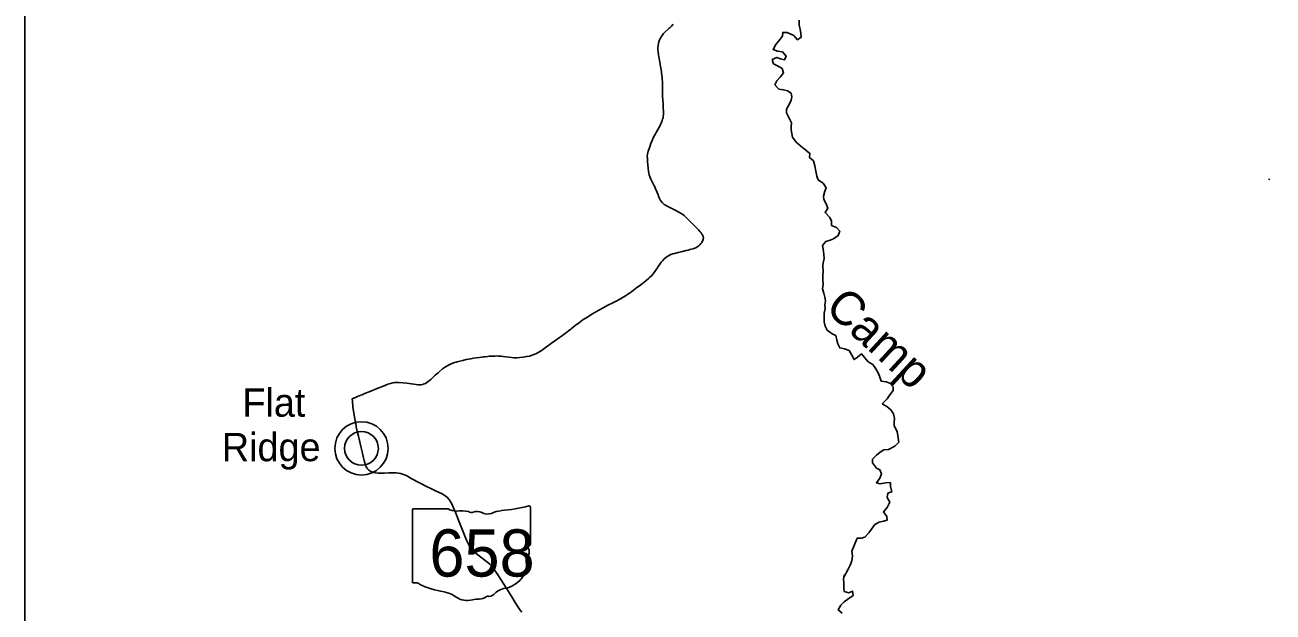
# Model space of a CAD drawing. Extents: x -29.6 to 34, y 0 to 22.
# Drawn here: x -29.583 to -26.314, y 9.402 to 10.939 of the extents above; entities that cross this region are included whole.
import ezdxf

# ---------------------------------------------------------------- set-up
doc = ezdxf.new("R2010")
doc.units = 0
for name, color, linetype in [('GM_X_Minor_River', 7, 'Continuous'), ('GM_X_Minor_River_Text', 7, 'Continuous'), ('GM_X_State_Route', 7, 'Continuous'), ('GM_X_State_Shield', 7, 'Continuous'), ('GM_X_Township_Road', 7, 'Continuous'), ('GM_X_Unincorporated', 7, 'Continuous'), ('GM_X_Unincorporated_Location', 7, 'Continuous'), ('GM_X_Unincorporated_Text', 7, 'Continuous'), ('SH_Text', 7, 'Continuous')]:
    doc.layers.add(name, color=color, linetype=linetype)

msp = doc.modelspace()

# ---------------------------------------------------------------- linework, layer by layer
at = {"layer": 'GM_X_Minor_River'}
msp.add_line((-26.3226, 10.534), (-26.3259, 10.5356), dxfattribs=at)
for points in [[(-27.5556, 10.9516), (-27.5555, 10.9388), (-27.5533, 10.9279), (-27.5507, 10.9162), (-27.5506, 10.9066), (-27.5601, 10.9001), (-27.5698, 10.911), (-27.5872, 10.9193), (-27.5986, 10.9196), (-27.5988, 10.91), (-27.609, 10.8971), (-27.617, 10.8874), (-27.624, 10.8749), (-27.6123, 10.8701), (-27.5995, 10.8688), (-27.5898, 10.8571), (-27.594, 10.8475), (-27.6043, 10.8502), (-27.6142, 10.8541), (-27.6262, 10.8483), (-27.6226, 10.8373), (-27.6101, 10.831), (-27.6001, 10.8247), (-27.5968, 10.8137), (-27.6056, 10.8019), (-27.6137, 10.7929), (-27.6192, 10.7822), (-27.6085, 10.771), (-27.5961, 10.7689), (-27.5861, 10.7666), (-27.5765, 10.7606), (-27.5746, 10.751), (-27.5767, 10.7418), (-27.5819, 10.7303), (-27.5885, 10.7186), (-27.5888, 10.7093), (-27.583, 10.6987), (-27.5754, 10.6831), (-27.5767, 10.6732), (-27.5763, 10.664), (-27.5744, 10.6547), (-27.5733, 10.6455), (-27.5632, 10.6324), (-27.5511, 10.6216), (-27.5382, 10.611), (-27.5279, 10.6026), (-27.5281, 10.5919), (-27.5181, 10.5831), (-27.5144, 10.57), (-27.5115, 10.5565), (-27.5089, 10.5427), (-27.5063, 10.5356)], [(-27.5063, 10.5356), (-27.5052, 10.5324), (-27.4927, 10.5244), (-27.4852, 10.5124), (-27.4887, 10.5035), (-27.4917, 10.491), (-27.4913, 10.4818), (-27.4844, 10.4708), (-27.4804, 10.4595), (-27.4878, 10.448), (-27.4749, 10.435), (-27.4712, 10.4251), (-27.4704, 10.4137), (-27.458, 10.4085), (-27.449, 10.3994), (-27.4535, 10.3876), (-27.4655, 10.3786), (-27.4747, 10.3757), (-27.486, 10.372), (-27.4944, 10.3613), (-27.4918, 10.3471), (-27.4906, 10.3378), (-27.4898, 10.3275), (-27.4929, 10.3165), (-27.4939, 10.3076), (-27.4927, 10.2952), (-27.4933, 10.2817), (-27.4932, 10.2707), (-27.4924, 10.2611), (-27.494, 10.2479), (-27.4907, 10.2366), (-27.4881, 10.2259), (-27.4866, 10.2167), (-27.4883, 10.206), (-27.4875, 10.1964), (-27.4902, 10.184), (-27.4897, 10.1726), (-27.49, 10.1619), (-27.487, 10.1506), (-27.482, 10.1396), (-27.4688, 10.1298), (-27.4595, 10.1256)], [(-27.4595, 10.1256), (-27.4566, 10.1136), (-27.454, 10.104), (-27.4493, 10.0934), (-27.4365, 10.0907), (-27.4248, 10.0869), (-27.4172, 10.0745), (-27.4118, 10.0628), (-27.4023, 10.069), (-27.3921, 10.0776), (-27.3839, 10.0674), (-27.3749, 10.0572), (-27.3628, 10.0498), (-27.3545, 10.0385), (-27.348, 10.0261), (-27.3444, 10.0166), (-27.3411, 10.0067), (-27.328, 10.0043), (-27.318, 10.0012), (-27.3094, 9.9917), (-27.3097, 9.9821), (-27.3181, 9.9706), (-27.3251, 9.9599), (-27.3377, 9.9473), (-27.326, 9.9396), (-27.3152, 9.9309), (-27.3088, 9.9206), (-27.3062, 9.9082), (-27.3064, 9.8986), (-27.3063, 9.8894), (-27.2991, 9.8742), (-27.2958, 9.8578), (-27.2946, 9.8468), (-27.3048, 9.8357), (-27.3217, 9.827), (-27.3334, 9.8269), (-27.3436, 9.8201), (-27.3527, 9.8129), (-27.3636, 9.8021), (-27.3635, 9.7925), (-27.3528, 9.7788), (-27.3439, 9.7742), (-27.3402, 9.7636), (-27.344, 9.7525), (-27.3531, 9.7404), (-27.3435, 9.7373), (-27.329, 9.7399), (-27.3163, 9.7407), (-27.3165, 9.7304), (-27.3132, 9.7166), (-27.3234, 9.7126), (-27.3251, 9.7015), (-27.3182, 9.6892), (-27.3248, 9.6756), (-27.3346, 9.6638), (-27.3257, 9.6521), (-27.3252, 9.6426), (-27.3344, 9.6396), (-27.3461, 9.6367), (-27.3577, 9.6309), (-27.3661, 9.6187), (-27.3731, 9.6094), (-27.3836, 9.5979), (-27.3935, 9.5953), (-27.4038, 9.5949)], [(-27.4384, 9.4934), (-27.4275, 9.5143), (-27.4215, 9.5243), (-27.4174, 9.5361), (-27.4157, 9.5486), (-27.4176, 9.561), (-27.4038, 9.5949)], [(-27.4374, 9.4988), (-27.4394, 9.4881), (-27.4383, 9.4789), (-27.4381, 9.4661), (-27.4377, 9.4558), (-27.4256, 9.452), (-27.4161, 9.4567), (-27.4142, 9.4454), (-27.4276, 9.4353), (-27.4378, 9.4285), (-27.4462, 9.4195), (-27.4532, 9.4073), (-27.4428, 9.3986)]]:
    msp.add_lwpolyline(points, dxfattribs=at)
at = {"layer": 'GM_X_State_Route'}
for points in [[(-27.9245, 10.8654), (-27.9251, 10.8689), (-27.9255, 10.8752), (-27.9254, 10.8792), (-27.9249, 10.8849), (-27.9239, 10.8905), (-27.9228, 10.895), (-27.9211, 10.8999), (-27.919, 10.9046), (-27.917, 10.908), (-27.9144, 10.9118), (-27.9115, 10.9157), (-27.9085, 10.919), (-27.899, 10.9278), (-27.8959, 10.9303)], [(-27.8959, 10.9303), (-27.8944, 10.9315), (-27.8898, 10.936), (-27.8852, 10.9413)], [(-27.9135, 10.7591), (-27.9133, 10.7717), (-27.9135, 10.7848), (-27.9136, 10.7907), (-27.9139, 10.7965), (-27.9143, 10.8024), (-27.9148, 10.807), (-27.9171, 10.8226), (-27.9184, 10.8301), (-27.9193, 10.8358), (-27.9204, 10.8416), (-27.9213, 10.8467), (-27.9222, 10.8513), (-27.923, 10.8559), (-27.9238, 10.8604), (-27.9242, 10.8633), (-27.9245, 10.8654)], [(-27.9436, 10.5356), (-27.9457, 10.5398), (-27.9481, 10.5466), (-27.95, 10.555), (-27.9511, 10.5638), (-27.9519, 10.573), (-27.9524, 10.581), (-27.953, 10.5896), (-27.9533, 10.5955), (-27.953, 10.6008), (-27.951, 10.6081), (-27.9479, 10.6176), (-27.9437, 10.6282), (-27.9406, 10.6362), (-27.9375, 10.6433), (-27.9343, 10.6498), (-27.9268, 10.6636), (-27.9208, 10.6743), (-27.9176, 10.6802), (-27.9169, 10.6817), (-27.9142, 10.6886), (-27.9133, 10.692), (-27.9121, 10.6958), (-27.9113, 10.7004), (-27.911, 10.7049), (-27.9109, 10.7113), (-27.9114, 10.723), (-27.9121, 10.7328), (-27.9133, 10.7518), (-27.9135, 10.7591)], [(-28.2821, 9.4012), (-28.2864, 9.4068), (-28.2898, 9.4117), (-28.2993, 9.4264), (-28.3085, 9.4412), (-28.3213, 9.4621), (-28.3294, 9.4749), (-28.3414, 9.4941), (-28.3449, 9.4994), (-28.3485, 9.5047), (-28.3541, 9.5128), (-28.359, 9.5193), (-28.3624, 9.5232), (-28.3661, 9.5269), (-28.3712, 9.5315), (-28.3777, 9.5368), (-28.3932, 9.5486), (-28.4013, 9.555), (-28.4063, 9.5595), (-28.4105, 9.5637), (-28.4139, 9.5677), (-28.4162, 9.5709), (-28.417, 9.572), (-28.4178, 9.5731), (-28.4198, 9.5761), (-28.421, 9.5782), (-28.4234, 9.5826), (-28.4267, 9.5896), (-28.4303, 9.5986), (-28.4479, 9.6424), (-28.455, 9.6603), (-28.4608, 9.6749), (-28.4633, 9.6807), (-28.4646, 9.6834), (-28.4667, 9.6875), (-28.4692, 9.6918), (-28.4716, 9.6952), (-28.4728, 9.6968), (-28.476, 9.7004), (-28.4795, 9.7036), (-28.4826, 9.7061), (-28.4866, 9.7087), (-28.4925, 9.712), (-28.5061, 9.7186), (-28.5188, 9.7244), (-28.533, 9.7312), (-28.545, 9.7371), (-28.5533, 9.7414), (-28.5569, 9.7433), (-28.5645, 9.7476), (-28.5731, 9.7526), (-28.5796, 9.7564), (-28.5851, 9.7593), (-28.5895, 9.7611), (-28.5942, 9.7628), (-28.5998, 9.7644), (-28.6055, 9.7654), (-28.611, 9.7661), (-28.6177, 9.7664), (-28.6303, 9.7662), (-28.6415, 9.7657), (-28.6515, 9.7654), (-28.6578, 9.7655), (-28.6652, 9.7663), (-28.6695, 9.7672), (-28.6723, 9.768), (-28.6762, 9.7695), (-28.6791, 9.771), (-28.6807, 9.772), (-28.6823, 9.7732), (-28.684, 9.7747), (-28.686, 9.7768), (-28.6872, 9.7783), (-28.6885, 9.7803), (-28.69, 9.783), (-28.6913, 9.786), (-28.6921, 9.7883), (-28.6933, 9.7921), (-28.695, 9.7983), (-28.6972, 9.8087), (-28.7, 9.8211), (-28.7034, 9.8353), (-28.7071, 9.8509), (-28.709, 9.8587), (-28.71, 9.8627), (-28.7129, 9.8754), (-28.7154, 9.8867), (-28.7161, 9.8902), (-28.7191, 9.9068), (-28.7227, 9.9287), (-28.7241, 9.938), (-28.7247, 9.9432), (-28.7252, 9.9494), (-28.7255, 9.9536), (-28.7259, 9.9597), (-28.716, 9.9642), (-28.7125, 9.9659), (-28.7083, 9.9679), (-28.7056, 9.969), (-28.704, 9.9696), (-28.7002, 9.9709), (-28.696, 9.9728), (-28.677, 9.9804), (-28.6608, 9.9867), (-28.6424, 9.9941), (-28.6326, 9.998), (-28.6259, 10.0002), (-28.6197, 10.0019), (-28.6156, 10.0025), (-28.6115, 10.003), (-28.6044, 10.003), (-28.5933, 10.002), (-28.5829, 10.0007), (-28.5588, 9.9974), (-28.553, 9.9969), (-28.549, 9.9968), (-28.5451, 9.9971), (-28.5417, 9.9977), (-28.538, 9.9989), (-28.5343, 10.0006), (-28.5309, 10.0026), (-28.5272, 10.0053), (-28.5206, 10.0109), (-28.5102, 10.0202), (-28.5085, 10.0218), (-28.5047, 10.0254), (-28.5013, 10.0285), (-28.4973, 10.032), (-28.4896, 10.0383), (-28.4848, 10.0417), (-28.4798, 10.0448), (-28.4742, 10.0479), (-28.4689, 10.0505), (-28.4608, 10.054), (-28.4576, 10.0552), (-28.4542, 10.0563), (-28.4514, 10.0572), (-28.4441, 10.059), (-28.4361, 10.0608), (-28.4275, 10.0626), (-28.4155, 10.0649), (-28.4085, 10.0661), (-28.4012, 10.0673), (-28.3931, 10.0685), (-28.3822, 10.0698), (-28.3776, 10.0703), (-28.3707, 10.0711), (-28.3678, 10.0714), (-28.3632, 10.0716), (-28.3586, 10.0718), (-28.3516, 10.0721), (-28.3481, 10.0722), (-28.3428, 10.0721), (-28.3388, 10.0717), (-28.3359, 10.0715), (-28.3307, 10.0707), (-28.3238, 10.0699), (-28.3163, 10.0689), (-28.3088, 10.0681), (-28.3025, 10.0677), (-28.295, 10.0677), (-28.2869, 10.0682), (-28.2788, 10.069), (-28.2696, 10.0705), (-28.2617, 10.0721), (-28.2545, 10.0741), (-28.248, 10.0766), (-28.2434, 10.0789), (-28.2389, 10.0814), (-28.2316, 10.0861), (-28.2206, 10.0938), (-28.2041, 10.1058), (-28.1932, 10.1136), (-28.1833, 10.1207), (-28.1781, 10.1244), (-28.1687, 10.1312), (-28.1594, 10.1382), (-28.1534, 10.1428), (-28.152, 10.1439), (-28.1465, 10.1482), (-28.1383, 10.1546), (-28.1355, 10.1568), (-28.1257, 10.1642), (-28.1209, 10.1675), (-28.1161, 10.1707), (-28.1076, 10.1758), (-28.0981, 10.1813), (-28.08, 10.1919), (-28.0675, 10.1992), (-28.0629, 10.2017), (-28.0552, 10.2058), (-28.0469, 10.21), (-28.0334, 10.2169), (-28.0236, 10.222), (-28.0166, 10.226), (-28.0087, 10.2309), (-28.0068, 10.2322), (-28, 10.2367), (-27.9949, 10.2405), (-27.9898, 10.2443), (-27.9852, 10.2478), (-27.9805, 10.2512), (-27.9739, 10.2561), (-27.966, 10.262), (-27.9618, 10.2652), (-27.9572, 10.2687), (-27.9497, 10.2751), (-27.9471, 10.2774), (-27.9415, 10.2832), (-27.9378, 10.2876), (-27.9336, 10.2931), (-27.929, 10.2998), (-27.9268, 10.3032), (-27.9262, 10.3042), (-27.9201, 10.3128), (-27.9166, 10.3175), (-27.9129, 10.322), (-27.9088, 10.3263), (-27.9058, 10.3291), (-27.9011, 10.3327), (-27.8976, 10.3348), (-27.8933, 10.3369), (-27.8873, 10.3393), (-27.8822, 10.3409), (-27.8726, 10.3434), (-27.8647, 10.3453), (-27.8613, 10.346), (-27.8517, 10.3483), (-27.8511, 10.3484), (-27.8466, 10.3496), (-27.8415, 10.3508), (-27.8343, 10.3527), (-27.8288, 10.3546), (-27.8263, 10.3558), (-27.8224, 10.358), (-27.8187, 10.3608), (-27.8158, 10.3635), (-27.8128, 10.367), (-27.8107, 10.3697), (-27.8093, 10.3721), (-27.808, 10.3746), (-27.807, 10.3773), (-27.8066, 10.3799), (-27.8064, 10.3814), (-27.8064, 10.3831), (-27.8066, 10.384), (-27.807, 10.3854), (-27.8076, 10.387), (-27.8087, 10.3891), (-27.81, 10.3911), (-27.8123, 10.3943), (-27.8148, 10.3974), (-27.8194, 10.4026), (-27.8286, 10.4122), (-27.84, 10.4237), (-27.8453, 10.4289), (-27.8515, 10.4349), (-27.8571, 10.4399), (-27.863, 10.4444), (-27.8704, 10.4489), (-27.8781, 10.4529), (-27.8906, 10.4589), (-27.8963, 10.4618), (-27.9016, 10.4644), (-27.9077, 10.468), (-27.9091, 10.4689), (-27.9144, 10.4737), (-27.9187, 10.4793), (-27.922, 10.4861), (-27.9239, 10.491), (-27.9251, 10.4942), (-27.9273, 10.5002), (-27.9298, 10.506), (-27.9314, 10.5097), (-27.9338, 10.515), (-27.9353, 10.5181), (-27.942, 10.5321), (-27.9436, 10.5356)]]:
    msp.add_lwpolyline(points, dxfattribs=at)
at = {"layer": 'GM_X_State_Shield'}
for p, q in [((-28.2596, 9.5787), (-28.2596, 9.6769)), ((-28.5686, 9.669), (-28.5686, 9.4814)), ((-28.4751, 9.6722), (-28.5656, 9.6722)), ((-28.2597, 9.5788), (-28.2596, 9.5787))]:
    msp.add_line(p, q, dxfattribs=at)
for centre, major_axis, start_param, end_param in [((-28.3697, 9.928), (0.3277, 0), 4.814394, 5.042369), ((-28.2631, 9.6773), (0.00344, 0), 6.141152, 7.989035), ((-28.5651, 9.6694), (0.00358, 0), 1.712693, 3.28349), ((-28.4536, 9.694), (0.0347, 0), 4.042523, 4.731795), ((-28.442, 9.5669), (0.1246, 0), 1.404758, 1.657858), ((-28.4137, 9.6704), (0.01, 0), 3.836095, 5.185415), ((-28.399, 9.6487), (0.0208, 0), 0.950623, 2.079405), ((-28.3722, 9.6784), (0.0251, 0), 4.081561, 5.145723), ((-28.3279, 9.6149), (0.0659, 0), 1.699011, 2.107814), ((-28.2633, 9.5784), (0.00368, 0), 5.05454, 6.418171), ((-28.2473, 9.5377), (0.0232, 0), 2.387724, 3.262537), ((-28.2604, 9.5715), (0.00532, 0), 1.883978, 3.671073), ((-28.2943, 9.5591), (0.032, 0), 5.934695, 6.695948), ((-28.3514, 9.5252), (0.082, 0), 5.101752, 6.440018), ((-28.5651, 9.481), (0.00361, 0), 3.00124, 4.508301), ((-28.5645, 9.5002), (0.0276, 0), 4.665946, 4.897461), ((-28.5589, 9.4706), (0.00994, 0), 0.519207, 1.627899), ((-28.4334, 9.6391), (0.2366, 0), 4.195997, 4.488961), ((-28.504, 9.3971), (0.074, 0), 0.823519, 1.323587), ((-28.3737, 9.4632), (0.0265, 0), 4.937069, 5.64225), ((-28.3168, 9.4287), (0.0449, 0), 1.647645, 2.488434), ((-28.4239, 9.4696), (0.047, 0), 4.026481, 4.996735), ((-28.3967, 9.4048), (0.0386, 0), 1.495662, 1.94098), ((-28.3933, 9.4556), (0.025, 0), 4.691044, 5.507374), ((-28.3707, 9.4374), (0.00705, 0), 1.147584, 2.315152)]:
    msp.add_ellipse(centre, major_axis=major_axis, ratio=0.8, start_param=start_param, end_param=end_param, dxfattribs=at)
at = {"layer": 'GM_X_Township_Road'}
msp.add_lwpolyline([(-27.9245, 10.8654), (-27.9242, 10.8633), (-27.9238, 10.8604), (-27.923, 10.8559), (-27.9222, 10.8513), (-27.9213, 10.8467), (-27.9204, 10.8416), (-27.9193, 10.8358), (-27.9184, 10.8301), (-27.9171, 10.8226), (-27.9148, 10.807), (-27.9143, 10.8024), (-27.9139, 10.7965), (-27.9136, 10.7907), (-27.9135, 10.7848), (-27.9133, 10.7717), (-27.9135, 10.7591)], dxfattribs=at)
at = {"layer": 'GM_X_Unincorporated'}
for radius in [0.0698, 0.0442]:
    msp.add_circle((-28.7019, 9.8303), radius, dxfattribs=at)
at = {"layer": 'GM_X_Unincorporated_Location'}
msp.add_line((-28.7019, 9.8303), (-28.7019, 9.8303), dxfattribs=at)
at = {"layer": 'SH_Text'}
msp.add_lwpolyline([(-29.5833, 13.2079), (-10.7478, 13.2079), (-10.7478, 1.0528), (-29.5833, 1.0528)], close=True, dxfattribs=at)

# ---------------------------------------------------------------- texts
at = {"layer": 'GM_X_Minor_River_Text'}
msp.add_text('Camp', height=0.08877, rotation=317.3793, dxfattribs=at).set_placement((-27.4911, 10.1942))
at = {"layer": 'GM_X_State_Shield'}
msp.add_text('658', height=0.1236, dxfattribs=at).set_placement((-28.524, 9.4946))
at = {"layer": 'GM_X_Unincorporated_Text'}
for s, p in [('Flat', (-29.0138, 9.9132)), ('Ridge', (-29.0677, 9.7967))]:
    msp.add_text(s, height=0.07404, rotation=0, dxfattribs=at).set_placement(p)

doc.saveas('drawing.dxf')
